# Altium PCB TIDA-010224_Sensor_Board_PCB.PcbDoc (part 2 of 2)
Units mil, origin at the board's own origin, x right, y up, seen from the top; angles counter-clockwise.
Board outline 1083.05 x 1167.48 mil, 4 copper layers (L1-Top Layer, L2-GND Layer, L3-PWR Layer, L4-Bottom Layer), stack 61.6 mil thick; 74 components, 35 nets, 283 pads, 146 vias.
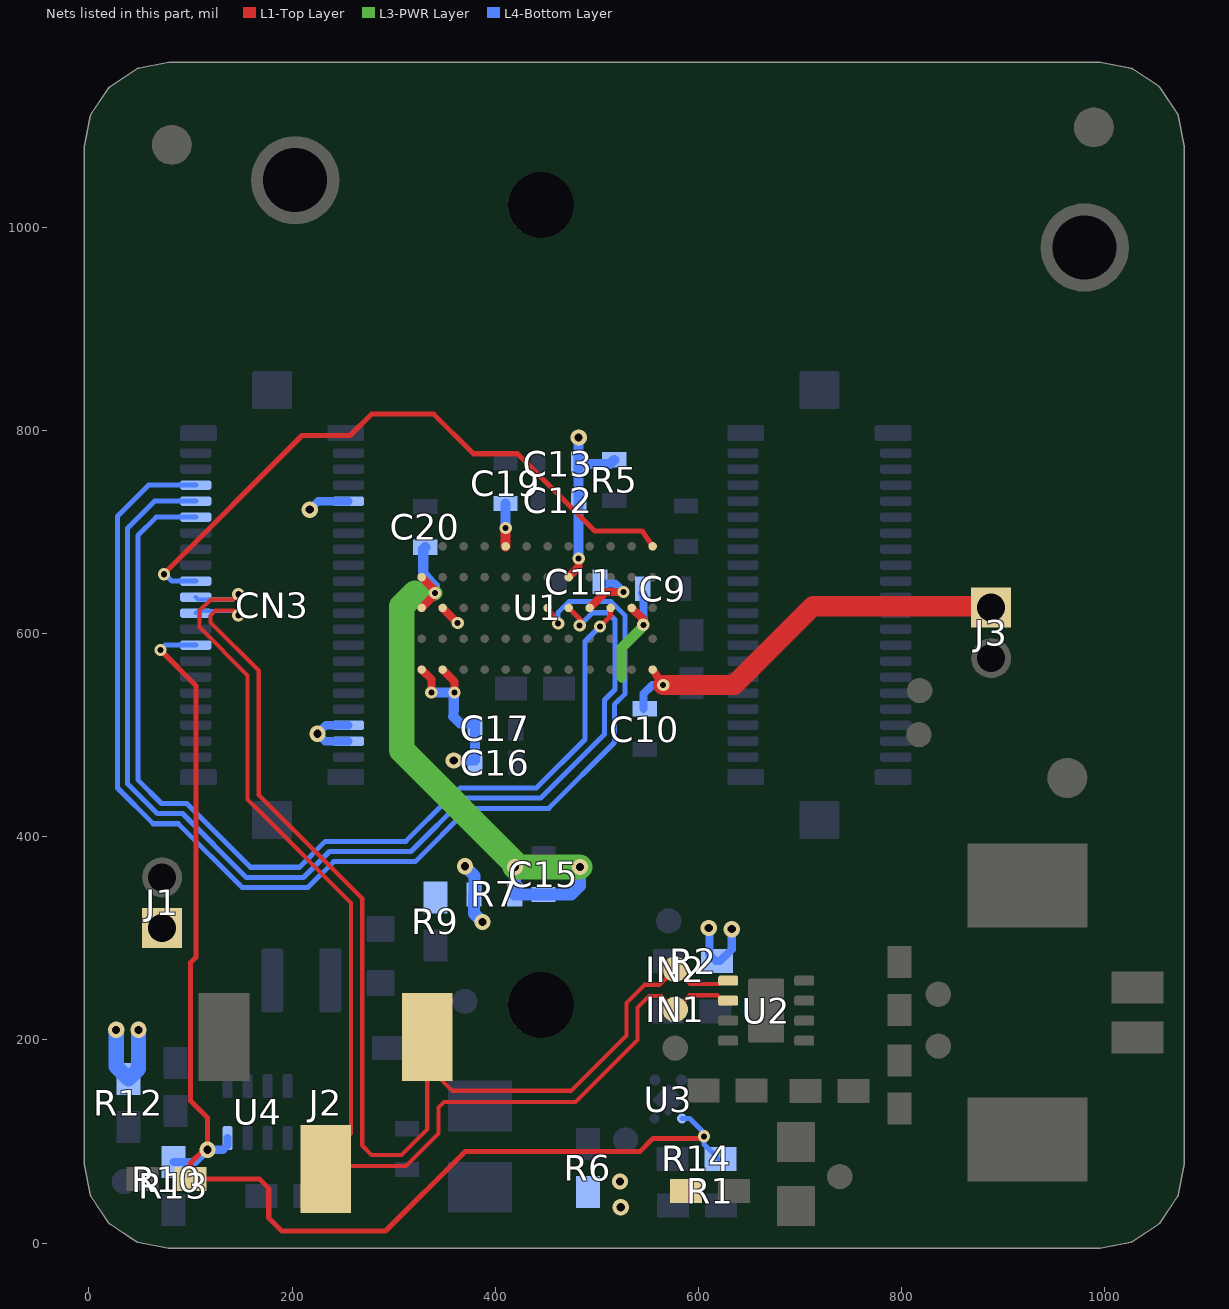
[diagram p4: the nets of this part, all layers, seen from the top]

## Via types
v1: diameter 16, hole 8, L1-Top Layer to L4-Bottom Layer, tented both sides, 103 vias
v2: diameter 12, hole 6, L1-Top Layer to L4-Bottom Layer, tented both sides, 40 vias
v3: diameter 20, hole 8, L1-Top Layer to L4-Bottom Layer, tented top, 2 vias
v4: diameter 20, hole 8, L1-Top Layer to L4-Bottom Layer, 1 vias

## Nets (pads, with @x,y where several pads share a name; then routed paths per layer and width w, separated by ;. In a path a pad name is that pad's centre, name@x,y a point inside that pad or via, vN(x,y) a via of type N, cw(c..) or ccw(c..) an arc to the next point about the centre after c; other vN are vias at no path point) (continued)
SN_IN1: CN3.21 IN1.1 J2.2 U2.6 | length 1239.7
  L1-Top Layer w4: v2(147,638.67) 142,633.67 119.89,633.67 108.74,622.53 108.74,606.29 156.11,558.92 156.11,436.64 167.11,425.64 258,334.76 258,107.8 233,82.8 J2.2@233,73.08 233,63.08 245.92,76 312,76 344,108 344,133.54 349.46,139 479,139 540,200 540,232 551.34,243.34 563.66,243.34 IN1.1@577,230 591,244 618.6,244 623.76,238.84 U2.6@629.21,238.84
  L4-Bottom Layer w4: CN3.21@105.11,635.81 107.49,633.44 141.77,633.44 v2(147,638.67)
SN_IN2: CN3.19 IN2.1 J2.3 U2.5 | length 1200.8
  L1-Top Layer w4: v2(147,618) 142.33,622.67 124.45,622.67 119.74,617.97 119.74,610.85 167.11,563.48 167.11,441.2 269,339.31 269,201.79 269,179.28 269,96 278,87 307.44,87 333,112.56 J2.3@333,175 ; J2.3@333,193 J2.3@333,175 ; U2.5@629.21,258.53 623.53,258.53 620,255 591.61,255 IN2.1@577,269.61 561.74,254.34 546.79,254.34 529,236.56 529,204.56 474.44,150 358,150 J2.3@333,175
  L4-Bottom Layer w4: CN3.19@105.11,620.06 107.49,622.44 142.56,622.44 v2(147,618)
SN_LDO_EN: CN3.15 R10.2 R13.2 R14.2 U3.3 U4.4 | length 1294.7
  L1-Top Layer w5: v2(70.31,583.87) 105.2,548.99 105.2,281.22 100,276.03 100,140.19 116.65,123.54 v1(116.65,92) 112.97,92 100,79.03 R10.2@100,63 ; R10.2@101.94,63 168,63 177,54 177,24.86 189.86,12 291.92,12 370.03,90.11 542.11,90.11 555,103 v2@604,103
  L4-Bottom Layer w5: v2(70.31,583.87) 75.01,588.57 CN3.15@105.11,588.57 ; U3.3@583.8,122.72 591.22,122.72 603.29,110.65 v2@603.29,103.71 ; v2(605.29,105.17) 605.29,97.25 R14.2@619.54,83
  L4-Bottom Layer w8: R13.2@83.28,80 104.65,80 v1(116.65,92) 132.13,92 136.47,96.34 U4.4@136.47,103.41
SN_PWDN: CN3.23 U1.A12 | length 636.5
  L1-Top Layer w5: v2(73.76,658.38) 73.76,659 209.76,795 257,795 278,816 339.46,816 378.46,777 421.8,777 497.78,701.01 544.5,701.01 U1.A12@554.83,685.85
  L4-Bottom Layer w5: v2(73.76,658.38) 74.91,658.38 81.73,651.56 CN3.23@105.11,651.56
SN_RST#: CN3.31 U1.C10 | length 974.2
  L1-Top Layer w5: v2@501.83,605.83 513.5,617.5 U1.C10@513.5,625.22
  L4-Bottom Layer w5: CN3.31@105.11,714.55 66.18,714.55 48.08,696.45 48.08,456.19 71.46,432.81 96.24,432.81 120.45,408.59 159.04,370 207.13,370 232.63,395.5 311.86,395.5 354.36,438 355.36,438 365.36,448 440.36,448 488.12,495.76 488.12,592.12 v2(503,607)
SN_SIO_C: CN3.33 U1.C8 | length 1078.5
  L1-Top Layer w5: U1.C8@472.16,625.22 484.86,612.51 483,610.65 v2(483,608)
  L4-Bottom Layer w5: CN3.33@105.11,730.3 64.55,730.3 38.08,703.83 38.08,452.04 67.32,422.81 92.09,422.81 154.9,360 211.28,360 236.78,385.5 317,385.5 369.5,438 444.5,438 507.35,500.85 507.35,534.54 517.73,544.91 517.73,613.45 510.68,620.5 495.5,620.5 v2(483,608)
SN_SIO_D: CN3.35 U1.C7 | length 1180.5
  L1-Top Layer w5: U1.C7@451.49,625.22 v2(461.82,610.06)
  L4-Bottom Layer w5: CN3.35@105.11,746.05 58.64,746.05 28.08,715.49 28.08,447.9 63.18,412.81 87.95,412.81 150.76,350 215.42,350 240.92,375.5 321.14,375.5 373.64,428 452.61,428 517.35,492.74 517.35,530.39 527.73,540.77 527.73,617.59 513.95,631.37 472.28,631.37 461.82,620.91 v2(461.82,610.06)
V1P8: C11.2 C12.2 C13.2 C19.2 CN3.4 CN3.6 R5.2 U1.A5 U1.B8 U1.C2 U1.C9 | length 371.5
  L1-Top Layer w8: U1.C2@348.14,625.22 v2@361.3,612.06 ; U1.B8@472.16,655.54 482,665.38 481.56,665.82 482,666.26 v2(482,674) ; U1.C9@492.83,625.22 508.6,641 v2(526,641) 524.16,641 v2@523.46,640.3
  L1-Top Layer w10: U1.A5@410.15,685.85 v2(410.15,703.85)
  L4-Bottom Layer w8: CN3.4@255.51,494.08 232.38,494.08 v1(225,501.46) 233.36,509.83 CN3.6@255.51,509.83 ; C11.2@507.5,649.17 517.83,649.17 v2(526,641)
  L4-Bottom Layer w10: C19.2@410,728 410,704 v2(410.15,703.85) ; v2@482,673.88 C12.2@482,731 C13.2@482,767 ; v1(482,793) C13.2@482,767 ; R5.2@517,771 513,767 C13.2@482,767
  other v2: 362.92,610.36
V2P8_AVDD: C9.2 C10.2 C16.2 C17.2 J3.1 R2.1 R7.2 R9.1 U1.C11 U1.E1 U1.E2 U1.E12 | length 833.6
  L1-Top Layer w8: U1.E1@327.47,564.59 337,555.06 v2(337,542) ; U1.E2@348.14,564.59 359.9,552.84 v2(359.9,541.95) ; U1.C11@534.16,625.22 545.65,613.73 v2(545.65,608.64) ; U1.E12@554.83,564.59 v2(565.17,549.43)
  L1-Top Layer w20: v2(565.17,549.43) 635.09,549.43 712.56,626.9 J3.1@875,626.9
  L3-PWR Layer w10: 524,557 524,585.65 544.5,606.14 545.65,607.3 v2(545.65,608.64)
  L4-Bottom Layer w8: C9.2@545,640 544.5,639.5 545.65,638.34 v2(545.65,608.64) ; C10.2@545.98,526 545.98,540.8 554.62,549.43 v2(565.17,549.43) ; v1(610.07,310.3) 610.63,309.75 610.63,284.45 610.35,284.17 616.92,277.6 R2.1@618.25,277.6 621.01,277.6 632.63,289.21 v1(632.63,309.06)
  L4-Bottom Layer w10: v2(337,542) 345.24,542 345.29,541.95 v2(359.9,541.95) 359.9,539.53 359,538.63 359,525.37 ; v1(359,475) 380,475 380,511.54 365.3,511.54 358.48,518.36 358.93,518.81 358.93,524.49 359.02,524.58 359.02,525.35
  L4-Bottom Layer w12: v1(370.04,371.01) 379.39,361.66 379.39,344.38 379,343.99 379.39,343.61 R7.2@379,343.22 379,324.61 v1(387.39,316.22)
V3P3: CN3.34 J1.1 R1.2 R6.2 R12.2 | length 147.5
  L4-Bottom Layer w8: v1(217.36,722) 225.66,730.3 CN3.34@255.51,730.3
  L4-Bottom Layer w15: v1(26.78,210) 26.78,173.84 R12.2@39,161.62 48.86,171.48 v1(48.86,210)
  other v1: 523.46,35.37 522.69,60.71
VPP: C15.2 C20.2 R7.1 U1.B1 U1.C1 | length 610.1
  L1-Top Layer w8: U1.C1@327.47,625.22 340.64,638.39 v2(340.64,639.99) 340.64,642.37 U1.B1@327.47,655.54
  L3-PWR Layer w15: 320.9,639.99 v2(340.64,639.99)
  L3-PWR Layer w25: 320.9,639.99 308,627.09 308,485.13 419.39,373.74 v1(419.39,370.22) v1(483.22,370.22)
  L4-Bottom Layer w10: C20.2@331,685 329,683 329,658.85 331.91,655.94 331.91,655.49 340.64,646.76 v2(340.64,639.99)
  L4-Bottom Layer w12: v1(419.39,370.22) 419.39,343.61 R7.1@419,343.22 C15.2@447.39,343.22 474.63,343.22 483.22,351.8 v1(483.22,370.22)
pads on no net: CN1.3 CN1.4 CN2.1 CN2.2 CN2.3 CN2.4 CN2.5 CN2.6 CN2.7 CN2.8 CN2.9 CN2.10 CN2.11 CN2.12 CN2.13 CN2.14 CN2.15 CN2.16 CN2.17 CN2.18 CN2.19 CN2.20 CN2.21 CN2.22 CN2.23 CN2.24 CN2.25 CN2.26 CN2.27 CN2.28 CN2.29 CN2.30 CN2.31 CN2.32 CN2.33 CN2.34 CN2.35 CN2.36 CN2.37 CN2.38 CN2.39 CN2.40 CN3.3 CN3.5 CN3.7 CN3.9 CN3.11 CN3.13 CN3.25 CN3.27 CN3.29 CN3.30 CN3.32 CN3.36 CN3.37 CN3.38 FID1.1 FID2.1 FID3.1 FID4.1 FID5.1 FID6.1 U1.A3 U1.A6 U1.A9 U1.A10 U1.B6 U1.B7 U1.B9 U1.C5 U1.C6 U1.D3 U1.D4 U1.D5 U1.D6 U1.D7 U1.D8 U1.D9 U2.9@666.62,211.28 U2.9@666.62,246.72

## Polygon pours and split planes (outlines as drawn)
GND on L4-Bottom Layer "L4-BOTTOM_LAYER_GND_P095" (solid, remove dead copper, pour order 95): 16,1091.19 62.27,1137.47 990.77,1137.47 cw(c990.77,1080.38) 1047.78,1077.5 1047.78,79.95 cw(c993.37,79.93) 1031.83,41.44 cw(c993.33,79.93) 993.33,25.49 40.51,25.49 16,50
V2P8_AVDD on L4-Bottom Layer "L4-Bottom Layer-V2P8_AVDD" (solid, remove dead copper, pour order 46): 321.14,375.5 321.14,329.3 329.44,321 385,321 389,325 389,375.99 381.99,383 328.64,383
NetFB1_2 on L4-Bottom Layer "L4-Bottom Layer-NetFB1_2" (solid, remove dead copper, pour order 26): 273.42,297.44 276.09,294.78 305.22,294.78 326,274 352,274 355,277 355,309.78 351.78,313 322.86,313 311.25,324.61 276.02,324.61 273.42,322
Net2P8V_1 on L4-Bottom Layer "L4-BOTTOM_LAYER_NET2P8V_1_P093" (solid, pour order 93): 228.67,274 228.67,287.67 232,291 292.24,291 301.96,281.29 301.96,260.83 307.79,255 317.15,255 339.3,255 342.8,251.51 342.8,222.8 319,199 319,170 335,154 335,105.19 329.81,100 286.41,100 269.12,100 266,103.12 266,136.69 259.68,143 191.55,143 188,146.55 188,169.78 192.82,174.6 218.83,174.6 228.67,184.44
Net3.3V_1 on L4-Bottom Layer "L4-BOTTOM_LAYER_NET3.3V_1_P070" (solid, pour order 70): 563.43,116.36 563.43,123.91 558.02,129.32 513.68,129.32 459.36,129.32 455.8,125.76 455.8,87.75 463.6,79.95 538.65,79.95 547,71.6 547,27.37 553.37,21 585.32,21 591.46,27.14 591.46,87.28 591.49,88.3 591.49,94.35 589.61,96.22 583.56,96.22 579.1,100.68
Net3P3V_1 on L4-Bottom Layer "L4-BOTTOM_LAYER_NET3P3V_1_P066" (solid, pour order 66): 52,95.92 60.22,87.71 60.22,59.51 65.57,54.15 100.99,54.15 108,61.16 108,66.05 117.89,75.93 145.63,75.93 146.72,77.01 167.01,77.01 170.98,80.98 170.87,110 180.31,110 180.31,69.69 186.89,63.11 186.89,15 40,15 15,40 15,132.04 30,132.04 49,132 52,129
V3P3 on L4-Bottom Layer "L4-BOTTOM_LAYER_V3P3_P002" (solid, pour order 2): 472.34,69.34 532.44,69.34 537,64.78 537,25.59 530.3,18.89 468.64,18.89 463.08,24.45 463.08,60.08
NetC18_1 on L4-Bottom Layer "L4-BOTTOM_LAYER_NETC18_1_P038" (solid, pour order 38): 324.62,175.79 324.62,202.3 326,203.68 359.32,203.68 404,159 414,159 425,148 425,106 418,99 353.61,99 349,103.61 349,151.41
Net2.8V_1 on L4-Bottom Layer "L4-BOTTOM_LAYER_NET2.8V_1_P004" (solid, pour order 4): 545.74,148.68 551.28,148.68 566.1,163.49 566.1,171.32 585.85,191.07 585.93,194.37 585.93,289.07 584,291 547,291 541,285 541,153.41
GND on L1-Top Layer "L1-TOP_LAYER_GND_P091" (solid, remove dead copper, pour order 91): 26.55,1101.74 57.45,1132.65 1007.57,1132.65 cw(c1007.58,1123.83) 1011,1131.96 cw(c988.65,1077.23) 1047.78,1077.5 1047.78,77.37 cw(c1002.2,65.07) 1035,31.11 cw(c1011.29,60.73) 993.92,27 54,27 26.55,54.45
V3P3 on L1-Top Layer "L1-TOP_LAYER_V3P3_P088" (solid, pour order 88): 512,69.34 512,30.41 522.41,20 594.7,20 608.22,33.52 608.22,76.11 592.98,91.35 534.01,91.35
NetC1_2 on L1-Top Layer "L1-TOP_LAYER_NETC1_2_P089" (solid, remove dead copper, pour order 89): 641,193.98 641,202.38 636.42,206.97 614.65,206.97 603.86,196.18 603.86,178.57 588.61,163.32 588.61,138.57 614.15,113.03 614.15,21.38 620.47,15 743,15 766,38 766,161.57 722.23,205.34 695.37,205.34 692,201.97 692,191.95 694.74,189.21 713.47,189.21 733,169.69 733,147.85 733,73 641,73
no net on L1-Top Layer "Top Layer-No Net" (solid, pour order 96): 258,313.74
V3P3 on L3-PWR Layer "L3-PWR_LAYER_V3P3_P082" (solid, pour order 82): 19.14,808.64 35.96,825.46 212.52,825.46 232,805.98 232,675.23 205,648.23 205,461.87 263,403.87 263,374 263,121.67 282.33,102.33 290.37,94.3 533.68,94.3 539.42,88.56 539.42,24.87 533.79,18.87 146.12,18.87 19.14,145.87 19.14,534.14
V2P8_AVDD on L3-PWR Layer "L3-PWR_LAYER_V2P8_AVDD_P086" (solid, remove dead copper, pour order 86): 340.54,565 319.5,543.97 319.5,50.51 355.01,15 989,15 1054.38,80.38 1054.38,600.62 999.07,655.93 581.39,655.93 490.46,565
V1P8 on L3-PWR Layer "L3-PWR_LAYER_V1P8_P084" (solid, remove dead copper, pour order 84): 219.95,474 210,483.95 210,643.28 238,671.28 238,1125 252,1139 540.27,1139 993.54,1139 1058,1074.54 1058,713 1020,675 589.27,675 482.27,568 331.52,568 315,551.48 315,488.52 300.48,474
no net on L3-PWR Layer "PWR Layer-No Net" (solid, pour order 87): 81.02,477.13
no net on Bottom Overlay (solid, pour order 48): 329,393
GND on L2-GND Layer "L2-GND_LAYER_GND_P074" (solid, remove dead copper, pour order 74): 26.55,1101.74 56.77,1131.96 993.32,1131.96 cw(c993.33,1077.51) 1031.83,1116.01 cw(c993.33,1077.51) 1047.78,1077.5 1047.78,79.95 cw(c993.33,79.95) 1031.83,41.44 cw(c993.32,79.95) 993.32,25.49 55.51,25.49 26.55,54.45

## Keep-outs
Keep-Out Layer:
  circle w1: c445.14,234.34 r62
  circle w1: c445.14,1021.75 r62
  text ".Layer_Name" at -2909.61,-3439.08 h60

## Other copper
L1-Top Layer:
  region net SN_CLK: 419,753
  text ".Layer_Name" at -2909.61,-3439.08 h60
L2-GND Layer:
  text ".Layer_Name" at -2891,-3432.01 h60
L3-PWR Layer:
  text ".Layer_Name" at -2878,-3434.01 h60
L4-Bottom Layer:
  pour cut-out: 637.88,102.81 637.88,111.86 611.93,137.8 598.52,137.8 598.52,117.12 612.83,102.81
  pour cut-out: 120.7,783 152,783 152,456 120.7,456
  pour cut-out: 239.93,783.31 203,783.31 203,455.25 239.93,455.25
  pour cut-out: 778.5,783.31 741.57,783.31 741.57,455.25 778.5,455.25
  pour cut-out: 659.27,783 690.57,783 690.57,456 659.27,456
  text ".Layer_Name" at -2909.61,-3439.08 h60

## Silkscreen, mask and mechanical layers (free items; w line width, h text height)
Top Overlay:
  lines w6: 508,144.42 508,144.95 529.5,166.44 544.9,166.44 ; 544.9,176 544.9,202.36 ; 566.98,286.07 552.82,286.07 544.9,278.15 544.9,166.44 ; 570.01,173.91 565.45,173.91 557.98,166.44 544.9,166.44 ; 587.97,285.65 593.48,285.65 601.52,277.61 601.52,190.83 601.52,188.99 601.03,188.99 591.57,179.53 ; 110.23,293.4 110.23,962.69 366.13,962.69 366.13,1021.43 cw(c444.87,1021.75) 523.61,1021.43 523.61,962.69 779.52,962.69 779.52,293.4 523.61,293.4 523.61,234.66 cw(c444.87,234.34) 366.13,234.66 366.13,293.4 110.23,293.4 ; 149.6,332.77 740.15,332.77 740.15,923.32 149.6,923.32 149.6,332.77 ; 412.26,29.22 424.48,17 494,17 506,29 506,146.42 504.42,148 412.26,148 412.26,29.22
  lines w10: 749,119 749,111.8 756.8,104 ; 758.31,54.45 769.55,54.45 781,43
  text ".PRJ_Number" at 258,1116.76 h30
  text "2.8V" at 967.08,611.25 h25
  text "GND" at 970,558.11 h25
  text "DVDD" at 835,484.33 h25
  text "3.3V" at 12,244 h25
  text "IN2" at 298,205 h30 r90
  text "EN" at 197,198 h30 r90
  text "GND" at 37,132 h30 r90
  text "IN1" at 186.89,15 h30 r90
  text ".Layer_Name" at -2909.61,-3439.08 h60
Bottom Overlay:
  lines w0: 948.04,83.62 948.04,84
  lines w6: 11,232 7,228 7,68 14,61 ; 379,255.95 388,275 ; 523.88,123.52 523.88,157.57 515.44,166 515.44,175.31 ; 584.01,330.71 586,336 ; 515.44,175.31 516.65,175.31 520.71,171.24 511.38,171.24 515.44,175.31
  text ".Layer_Name" at -2909.61,-3439.08 h60
Top Paste:
  text ".Layer_Name" at -2909.61,-3439.08 h60
Bottom Paste:
  text ".Layer_Name" at -2909.61,-3439.08 h60
Top Solder:
  text ".Layer_Name" at -2909.61,-3439.08 h60
  text ".Layer_Name" at -2909.61,-3439.08 h60
Bottom Solder:
  region: 550.53,114.55 564.14,114.55 564.14,125.17 555.09,134.21 550.53,134.21
  region: 589.7,114.2 576.09,114.2 576.09,124.82 585.14,133.86 589.7,133.86
  region: 589.92,167.68 576.31,167.68 576.31,157.06 585.35,148.02 589.92,148.01
  region: 550.48,167.68 564.08,167.68 564.08,157.06 555.04,148.02 550.48,148.01
  text ".Layer_Name" at -2909.61,-3439.08 h60
Drill Guide:
  text ".Layer_Name" at -2909.61,-3439.08 h60
M1 Board Outline:
  lines w10: 48.86,1151.01 23.31,1133.94 ; 0.25,78.74 6.24,48.6 ; 0.25,78.74 6.24,48.6 ; 0.25,78.74 0.25,1078.26 ; 0.25,1078.26 6.24,1108.39 ; 0.25,1078.26 6.24,1108.39 ; 6.24,48.6 23.31,23.05 ; 6.24,48.6 23.31,23.05 ; 6.24,1108.39 23.31,1133.94 ; 6.24,1108.39 23.31,1133.94 ; 23.31,23.05 48.86,5.98 ; 23.31,23.05 48.86,5.98 ; 23.31,1133.94 49.64,1151.52 79.45,1157.45 994.52,1157.45 ; 48.86,5.98 78.99,-0.01 ; 48.86,5.98 78.99,-0.01 ; 79,0 994.52,0 ; 994.52,0 1024.66,5.99 ; 994.52,0 1024.66,5.99 ; 994.52,1157.45 1024.66,1151.46 ; 994.52,1157.45 1024.66,1151.46 ; 1024.66,5.99 1050.21,23.06 ; 1024.66,5.99 1050.21,23.06 ; 1024.66,1151.46 1050.21,1134.39 ; 1024.66,1151.46 1050.21,1134.39 ; 1050.21,23.06 1067.28,48.61 ; 1050.21,23.06 1067.28,48.61 ; 1050.21,1134.39 1067.28,1108.85 ; 1050.21,1134.39 1067.28,1108.85 ; 1067.28,48.61 1073.27,78.74 ; 1067.28,48.61 1073.27,78.74 ; 1067.28,1108.85 1073.27,1078.72 ; 1067.28,1108.85 1073.27,1078.72 ; 1073.27,78.74 1073.27,1078.72
M2 Board Dimensions:
  rectangle: -3361.61,-2980.59 -2986.61,-2855.59
  rectangle: -3486.61,-2855.59 -3361.61,-2730.59
  lines w7: -3486.61,-2855.59 -2486.61,-2855.59 ; -3361.61,-2980.59 -3361.61,-2730.59 ; -3236.61,-2980.59 -3236.61,-2730.59 ; -2986.61,-2980.59 -2986.61,-2730.59 ; -2736.61,-2980.59 -2736.61,-2730.59 ; -3486.61,-2980.59 -3486.61,-2730.59 -2486.61,-2730.59 -2486.61,-2980.59 -3486.61,-2980.59
M3 3D STEP Top:
  text ".Layer_Name" at -2909.61,-3439.08 h60
M4 3D STEP Bottom:
  text ".Layer_Name" at -2909.61,-3439.08 h60
M5 Assembly Top:
  circle w10: c879,618.44 r9.85
  lines w10: -3778.61,-3510.76 2821.39,-3510.76 ; -3778.61,-3307.42 2823.39,-3307.42 ; -3778.61,-3104.09 -3778.61,-3714.09 226.39,-3714.09 2823.39,-3714.09 2823.39,-3104.09 -3778.11,-3104.09 -3778.11,-3714.09 -2202.61,-3714.09 ; -1313.61,-3714.09 -1313.61,-3104.09 ; -46.61,-3307.42 -46.61,-3104.09 ; 793.39,-3307.42 793.39,-3104.09 ; 1415.39,-3720.59 1415.39,-3517.76
  text "COMPONENTS MARKED 'DNP' SHOULD NOT BE POPULATED." at -2333.11,-2899.09 h18
  text "ASSEMBLY VARIANT:" at -2333.61,-3014.59 h18
  text ".VariantName" at -1297.61,-3014.59 h18
  text ".PRJ_Number" at -1032,-3235 h18
  text "PCB VIEWED FROM TOP SIDE" at -3715.11,-3236.26 h18
  text "BOARD #:" at -1238.61,-3236.26 h18
  text "REV:" at 151.39,-3236.26 h18
  text ".PCB_Rev" at 246,-3237 h18
  text "SVN REV:" at 989.39,-3236.26 h18
  text ".VersionControl_RevNumber" at 1495.39,-3236.26 h18
  text ".Layer_Name" at -2908,-3434.01 h18
  text "LAYER NAME =" at -3715.11,-3439.08 h18
  text "TID #:" at -1238.61,-3439.59 h18
  text ".TID" at -1105,-3440 h18
  text "PLOT NAME =" at -3715.11,-3644.92 h18
  text ".plot_File_Name" at -2909.61,-3644.92 h18
  text "GENERATED    :" at -1236.61,-3644.92 h18
  text ".Print_Date" at -367.11,-3644.92 h18
  text ".Print_Time" at 361.89,-3644.92 h18
  text "TEXAS INSTRUMENTS" at 1626.39,-3644.92 h18
M6 Assembly Bottom:
  circle w10: c132.13,177.92 r5.39
  lines w10: -3779.11,-3307.92 2822.89,-3307.92 ; -3777.11,-3511.26 2822.89,-3511.26 ; -2371.11,-3721.09 -2371.11,-3518.26 ; -1749.11,-3307.92 -1749.11,-3104.59 ; -909.11,-3307.92 -909.11,-3104.59 ; 357.89,-3714.59 357.89,-3104.59 ; 1246.89,-3714.59 2822.39,-3714.59 2822.39,-3104.59 -3779.11,-3104.59 -3779.11,-3714.59 -1182.11,-3714.59 2822.89,-3714.59 2822.89,-3104.59
  text "COMPONENTS MARKED 'DNP' SHOULD NOT BE POPULATED." at 2615.39,-2898.59 h18
  text ".VariantName" at 1571.39,-3014.59 h18
  text "ASSEMBLY VARIANT:" at 2610.39,-3014.59 h18
  text ".PRJ_Number" at 99.39,-3233.76 h18
  text ".VersionControl_RevNumber" at -2451.11,-3236.76 h18
  text "SVN REV:" at -1945.11,-3236.76 h18
  text ".PCB_Rev" at -1209.61,-3236.76 h18
  text "REV:" at -1107.11,-3236.76 h18
  text "BOARD #:" at 282.89,-3236.76 h18
  text "PCB VIEWED FROM BOTTOM SIDE" at 2759.39,-3236.76 h18
  text ".Layer_Name" at 2509,-3413 h18
  text "LAYER NAME =" at 2754,-3414 h18
  text ".TID" at 142.39,-3435.09 h18
  text "TID #:" at 282.89,-3440.09 h18
  text "TEXAS INSTRUMENTS" at -2582.11,-3645.42 h18
  text ".Print_Time" at -1317.61,-3645.42 h18
  text ".Print_Date" at -588.61,-3645.42 h18
  text "GENERATED    :" at 280.89,-3645.42 h18
  text ".plot_File_Name" at 1953.89,-3645.42 h18
  text "PLOT NAME =" at 2759.39,-3645.42 h18
M9 Title Sheet:
  drawing of 57 lines, arcs and shapes, not listed
  text "1" at -2746.78,5455.91 h70
  text "2" at -251.11,5455.91 h70
  text "3" at 2238.23,5455.91 h70
  text "4" at 4744.9,5455.91 h70
  text "5" at 7243.89,5455.91 h70
  text "6" at 9748.89,5455.91 h70
  text "A" at -3903.11,4312.91 h70
  text "A" at 10896.89,4312.91 h70
  text "A" at 10898.91,4312.13 h70
  text "B" at -3903.11,1932.91 h70
  text "B" at 10896.89,1932.91 h70
  text "B" at 10898.91,1932.13 h70
  text "C" at -3903.11,-442.09 h70
  text "C" at 10896.89,-442.09 h70
  text "C" at 10898.91,-442.87 h70
  text "PROJECT TITLE:" at 7856.89,-2303.09 h45
  text ".PRJ_Title" at 7906.89,-2436.42 h70
  text "DESIGNED FOR:" at 7856.89,-2604.09 h45
  text ".PRJ_Customer" at 7906.89,-2744.09 h70
  text "D" at -3903.11,-2812.09 h70
  text "D" at 10896.89,-2812.09 h70
  text "FILE NAME:" at 7856.89,-2904.09 h45
  text ".PCB_File_Name_No_Path" at 7906.89,-3024.09 h70
  text "Texas Instruments (TI) and/or its licensors do not warrant the accuracy or completeness of this specification" at 2887.39,-3185.93 h45
  text "ENGINEER:" at 7856.89,-3194.09 h45
  text "LAYOUT BY:" at 9361.89,-3194.09 h45
  text "or any information contained therein. TI and/or its licensors do not warrant that this design will meet" at 2842.4,-3298.59 h45
  text ".PRJ_Engineer" at 7906.89,-3349.08 h70
  text ".PCB_Layout" at 9412.39,-3349.08 h70
  text "the specifications, will be suitable for your application or fit for any particular purpose, or will operate in" at 2842.4,-3411.26 h45
  text "ALTIUM DESIGNER VERSION:" at 9361.89,-3504.09 h45
  text "an implementation. TI and/or its licensors do not warrant that the design is production worthy. You should" at 2842.4,-3523.92 h45
  text "completely validate and test your design implementation to confirm the system functionality for your application." at 2887.39,-3636.59 h45
  text ".print_Scale" at 7906.89,-3637.42 h70
  text ".Application_BuildNumber" at 9412.39,-3637.42 h70
  text "1" at -2746.78,-3844.09 h70
  text "2" at -251.11,-3844.09 h70
  text "3" at 2238.23,-3844.09 h70
  text "4" at 4744.9,-3844.09 h70
  text "5" at 7243.89,-3844.09 h70
  text "6" at 9748.89,-3844.09 h70
M10 Fab Notes:
  drawing of 243 lines, arcs and shapes, not listed
  text "DESIGN INFORMATION" at 8884.86,4219.35 h60
  text "(REFER ALSO ARRAY/PANEL PROFILING INFORMATION)" at 8533.35,4053.28 h60
  text "BOARD SIZE" at 7847.35,4048.99 h60
  text "1073.02mil" at 8323.37,3934.63 h60
  text "X" at 8815.35,3921.17 h60
  text "1157.45mil" at 9022,3919.99 h60
  text "Number of Layers :" at 8250.34,3723.99 h60
  text "4" at 9322.89,3718.99 h60
  text "4" at 9323.82,3587.2 h60
  text "MIN. TRACK WIDTH:" at 8250.34,3584.99 h60
  text "MIL" at 9501.34,3584.99 h60
  text "4" at 9323.37,3460.63 h60
  text "MIN. CLEARANCE:" at 8250.34,3452.99 h60
  text "MIL" at 9501.34,3452.99 h60
  text "6" at 9325.82,3333.2 h60
  text "MIN. VIA DRILL SIZE:" at 8250.34,3320.99 h60
  text "MIL" at 9501.34,3320.99 h60
  text "EXTERNAL" at 9242.89,3190.99 h60
  text "3 MIL" at 8945.35,3179.28 h60
  text "MINIMUM ANNULAR RING" at 7921.11,3175 h60
  text "PER" at 8121.11,3057 h60
  text "IPC-D-275 CLASS 2 LEVEL C" at 8341.11,3056.99 h60
  text "+/-" at 9436.89,2944 h60
  text "MIL, HOLES" at 9829.34,2944.71 h60
  text "+/-" at 10290.89,2944 h60
  text "REGISTRATION TOLERANCES:" at 7921.11,2938.99 h60
  text "METAL" at 9120.89,2938.99 h60
  text "5" at 9697.09,2939 h60
  text "3" at 10530.09,2939 h60
  text "MIL" at 10646.34,2938.99 h60
  text "MATERIAL:" at 7846.35,2729.54 h60
  text "FR-4 High Tg" at 8832.79,2589.2 h60
  text "X" at 8673.89,2580.99 h60
  text "FR-408" at 8267.35,2580.63 h60
  text "OTHER" at 9755.35,2580.63 h60
  text "63 MIL (1.6mm) +/-10%" at 8587.45,2417.92 h60
  text "THICKNESS:" at 7921.11,2413.63 h60
  text "X" at 8459.28,2413.63 h60
  text "OTHER" at 9872.35,2413.63 h60
  text "TOLERANCE:" at 7921.11,2255.63 h60
  text "X" at 8760.42,2255.63 h60
  text "ANSI IPC-6012 TYPE 3 CLASS 2" at 8947.36,2255.63 h60
  text "OTHER +/-" at 8947.35,2099.63 h60
  text "BOW & TWIST:" at 7921.11,1942.63 h60
  text "X" at 8760.42,1942.63 h60
  text "ANSI IPC-6012 TYPE 3 CLASS 2" at 8947.36,1942.63 h60
  text "OTHER +/-" at 8947.35,1784.13 h60
  text "COPPER THICKNESS (FINISHED):" at 7846.35,1648.63 h60
  text "1.4MIL (1oz)" at 8726.34,1495.92 h60
  text "2MIL (1.4oz)" at 9493.35,1495.92 h60
  text "2.8MIL (2oz)" at 10220.35,1495.92 h60
  text "OUTER:" at 8203.35,1491.63 h60
  text "X" at 8597.89,1490.99 h60
  text "X" at 8593.89,1340.99 h60
  text "1.4MIL (1oz)" at 8726.34,1338.92 h60
  text "2.8MIL (2oz)" at 9493.35,1338.92 h60
  text "N/A" at 10219.89,1339.28 h60
  text "INNER SIGNAL:" at 7914.26,1334.63 h60
  text "DRILLING:" at 7846.35,1195.63 h60
  text "REFERENCE:" at 7921.11,1078.63 h60
  text "X" at 8569.35,1078.63 h60
  text "AS SHOWN" at 8756.34,1078.63 h60
  text "X" at 9470.35,1078.63 h60
  text "NC_DRILL FILES" at 9607.34,1078.63 h60
  text "PTH MIN COPPER THICKNESS:" at 7921.11,920.63 h60
  text "X" at 9271.35,920.63 h60
  text "1MIL" at 9408.34,920.63 h60
  text "OTHER" at 9905.35,920.63 h60
  text "BOARD FINISH:" at 7846.35,761.63 h60
  text "SILKSCREEN:" at 8001.57,643.63 h60
  text "X" at 8950.35,643.63 h60
  text "TOP" at 9076.34,643.63 h60
  text "X" at 9460.35,643.63 h60
  text "BOTTOM" at 9587.34,643.63 h60
  text "SILKSCREEN COLOR:" at 8001.57,476.63 h60
  text "X" at 8949.3,476.63 h60
  text "WHITE" at 9076.34,476.63 h60
  text "OTHER" at 9587.34,476.63 h60
  text "BLUE" at 9793,319.8 h60
  text "X" at 9078.31,308.44 h60
  text "GREEN" at 9205.34,308.44 h60
  text "SOLDER RESIST COLOR:" at 8001.57,306.63 h60
  text "OTHER" at 9825.35,147.44 h60
  text "IMPEDANCE DETAILS - ALL DIMENSIONS IN MILS" at 3100.5,137.5 h60
  text "X" at 9076.06,132.53 h60
  text "MATTE" at 9194.06,132.53 h60
  text "100ohm DIFFERENTIAL" at 3691.5,45.5 h40
  text "IMPEDANCE CONTROL" at 3694.5,8.5 h40
  text "+/- 10%" at 3804.5,-26.5 h40
  text "IMMERSION GOLD (ENIG)" at 8907.34,-41.08 h60
  text "ENEPIG" at 10244.89,-44.37 h60
  text "SURFACE FINISH:" at 7846.35,-45.37 h60
  text "X" at 8720.4,-45.37 h60
  text "TRACE WIDTH / SPACE" at 3667.5,-85.5 h40
  text "LAYER#" at 2970.5,-89.5 h40
  text "LAYER 1 - PRIMARY SIDE - SIGNAL" at 2939.5,-159.5 h40
  text "4.00/7.00" at 3754,-160 h40
  text "IMM. TIN/SILVER OR EQUIV" at 8175.89,-202.37 h60
  text "OTHER" at 9607.35,-202.37 h60
  text "LAYER 2 - GND" at 2944,-254 h40
  text "LAYER 3 - GND" at 2948,-336 h40
  text "ARRAY/PANEL:" at 7846.35,-381.37 h60
  text "X" at 8717,-383 h60
  text "CUT AND TRIM PER MECH LAYER 1" at 8907.35,-385.65 h60
  text "4.00/7.00" at 3756,-420 h40
  text "LAYER 4 - SECONDARY SIDE - SIGNAL" at 2942,-423 h40
  text "N.C. ROUTE" at 8907.34,-537.37 h60
  text "V. SCORE" at 9773.35,-537.37 h60
  text "CERTIFICATION:" at 7846.35,-674.37 h60
  text "MATERIALS AND WORKMANSHIP FOR ALL PCBS" at 8571.35,-674.37 h60
  text "TO MEET OR EXCEED THE REQUIREMENTS OF:" at 8571.35,-772.37 h60
  text "FAB Note:" at 2743.76,-796.49 h150
  text "X" at 8197.85,-908.87 h60
  text "ANSI IPC-A-600F CLASS ->" at 8336.85,-908.87 h60
  text "X" at 9975.9,-908.87 h60
  text "2" at 10094.85,-908.87 h60
  text "1" at 9779.85,-910.37 h60
  text "3" at 10448.85,-910.37 h60
  text "1.ITS AN IMPEDANCE CONTROLLED BOARD" at 2741.15,-924 h60
  text "2.ALL VIAS ARE  TENTED EXCEPT THERMAL VIAS" at 2741.15,-1051.25 h60
  text "X" at 8199.9,-1068.37 h60
  text "UL 94V-0" at 8336.85,-1068.37 h60
  text "X" at 9011.9,-1068.37 h60
  text "RoHS" at 9148.85,-1068.37 h60
  text "OTHER" at 9793.25,-1068.37 h60
  text "PER ORDER" at 10190.31,-1068.37 h60
  text "3.Vendor may adjust soldermask wherever the soldermask pads are same size(1:1)" at 2733.15,-1187.72 h150
  text "VIA TENTING:" at 9063.89,-1202.01 h60
  text "X" at 9826.37,-1205.37 h60
  text "ADDITIONAL REQUIREMENTS:" at 7846.35,-1209.37 h60
  text "YES" at 9613.55,-1211.09 h60
  text "NO" at 9978.36,-1216.31 h60
  text "MICROSECTION:" at 7921.11,-1324.37 h60
  text "YES" at 8826.85,-1324.37 h60
  text "IMPEDANCE CONTROL:" at 9085.89,-1331.01 h60
  text "YES" at 10069.89,-1332.01 h60
  text "X" at 10288,-1332 h60
  text "NO" at 10445.36,-1349.31 h60
  text "As per the manufacturing capabilities and all other soldermask pads  / shall not be modified," at 2919.74,-1425.25 h150
  text "REQUIRED" at 9688.34,-1480.51 h60
  text "BARE BOARD ELEC. TEST:" at 7921.11,-1483.37 h60
  text "NONE" at 9226.85,-1483.37 h60
  text "X" at 9561.35,-1483.37 h60
  text "PER ORDER" at 10280.35,-1483.37 h60
  text "MANUFACTURER'S UL:" at 7921.11,-1640.37 h60
  text "RAIL" at 9086.85,-1644.65 h60
  text "METAL" at 9578.66,-1644.65 h60
  text "X" at 9953.89,-1645.01 h60
  text "SILK" at 10090.34,-1644.65 h60
  text "Provided no adjscent copper is exposed and  no conflict is  produced  / with any stated\"Via tenting/covering requirements\"" at 2919.34,-1659.79 h150
M11 Gerber Information:
  lines w10: -3778.61,-3510.76 2821.39,-3510.76 ; -3778.61,-3307.42 2823.39,-3307.42 ; -3778.61,-3104.09 -3778.61,-3714.09 226.39,-3714.09 2823.39,-3714.09 2823.39,-3104.09 -3778.11,-3104.09 -3778.11,-3714.09 -2202.61,-3714.09 ; -1313.61,-3714.09 -1313.61,-3104.09 ; -46.61,-3307.42 -46.61,-3104.09 ; 793.39,-3307.42 793.39,-3104.09 ; 1415.39,-3720.59 1415.39,-3517.76
  text ".PRJ_Number" at -754,-3223 h50
  text "REV:" at 276.39,-3231.26 h60
  text ".PCB_Rev" at 567.89,-3231.26 h60
  text "ALL ARTWORK VIEWED FROM TOP SIDE" at -3715.11,-3236.26 h60
  text "BOARD #:" at -1238.61,-3236.26 h60
  text "SVN REV:" at 989.39,-3236.26 h60
  text ".VersionControl_RevNumber" at 1495.39,-3236.26 h60
  text "LAYER NAME =" at -3715.11,-3439.08 h60
  text "TID #:" at -1238.61,-3439.59 h60
  text ".TID" at -693.11,-3439.59 h60
  text "PLOT NAME =" at -3715.11,-3644.92 h60
  text ".plot_File_Name" at -2909.61,-3644.92 h30
  text "GENERATED    :" at -1236.61,-3644.92 h60
  text ".Print_Date" at -367.11,-3644.92 h60
  text ".Print_Time" at 361.89,-3644.92 h60
  text "TEXAS INSTRUMENTS" at 1626.39,-3644.92 h60
M12 Stackup:
  drawing of 295 lines, arcs and shapes, not listed
  text "Layer" at 2052.09,3568 h60
  text "Name" at 2462,3568 h60
  text "Material" at 3451.73,3568 h60
  text "Thickness" at 4311.49,3568 h60
  text "Constant" at 4961.33,3568 h60
  text "Board Layer Stack" at 5531.19,3568 h60
  text "1" at 2052.09,3448 h60
  text "Top Overlay" at 2462,3448 h60
  text "2" at 2052.09,3328 h60
  text "Top Solder" at 2462,3328 h60
  text "Solder Resist" at 3451.73,3328 h60
  text "0.30mil" at 4311.49,3328 h60
  text "3.5" at 4961.33,3328 h60
  text "3" at 2052.09,3208 h60
  text "L1-Top Layer" at 2462,3208 h60
  text "Copper" at 3451.73,3208 h60
  text "1.40mil" at 4311.49,3208 h60
  text "4" at 2052.09,3088 h60
  text "Dielectric1" at 2462,3088 h60
  text "FR-4 High Tg" at 3451.73,3088 h60
  text "8.00mil" at 4311.49,3088 h60
  text "4.5" at 4961.33,3088 h60
  text "5" at 2052.09,2968 h60
  text "L2-GND Layer" at 2462,2968 h60
  text "Copper" at 3451.73,2968 h60
  text "1.40mil" at 4311.49,2968 h60
  text "6" at 2052.09,2848 h60
  text "Dielectric 2" at 2462,2848 h60
  text "FR-4 High Tg" at 3451.73,2848 h60
  text "40.00mil" at 4311.49,2848 h60
  text "4.5" at 4961.33,2848 h60
  text "7" at 2052.09,2728 h60
  text "L3-PWR Layer" at 2462,2728 h60
  text "Copper" at 3451.73,2728 h60
  text "1.40mil" at 4311.49,2728 h60
  text "8" at 2052.09,2608 h60
  text "Dielectric 3" at 2462,2608 h60
  text "FR-4 High Tg" at 3451.73,2608 h60
  text "8.00mil" at 4311.49,2608 h60
  text "4.5" at 4961.33,2608 h60
  text "9" at 2052.09,2488 h60
  text "L4-Bottom Layer" at 2462,2488 h60
  text "Copper" at 3451.73,2488 h60
  text "1.40mil" at 4311.49,2488 h60
  text "10" at 2052.09,2368 h60
  text "Bottom Solder" at 2462,2368 h60
  text "Solder Resist" at 3451.73,2368 h60
  text "0.30mil" at 4311.49,2368 h60
  text "3.5" at 4961.33,2368 h60
  text "11" at 2052.09,2248 h60
  text "Bottom Overlay" at 2462,2248 h60
M13 Component Bodies Top:
  text ".Layer_Name" at -2909.61,-3439.08 h60
M14 Component Bodies Bottom:
  text ".Layer_Name" at -2909.61,-3439.08 h60
M15 Courtyards Top:
  text ".Layer_Name" at -2909.61,-3439.08 h60
M16 Courtyards Bottom:
  text ".Layer_Name" at -2909.61,-3439.08 h60
Drill Drawing:
  circle w10: c2081.72,1620.96 r27.63
  lines w10: 2054.09,1234.19 2067.9,1234.19 2067.9,1220.37 2095.53,1220.37 2095.53,1234.19 2109.34,1234.19 2109.34,1261.81 2095.53,1261.81 2095.53,1275.63 2067.9,1275.63 2067.9,1261.81 2054.09,1261.81 2054.09,1234.19 ; 2054.09,1344.69 2109.34,1344.69 2109.34,1399.95 2054.09,1399.95 2054.09,1344.69 ; 2054.09,1469.01 2081.72,1482.83 2109.34,1469.01 2095.53,1496.64 2109.34,1524.27 2081.72,1510.45 2054.09,1524.27 2067.9,1496.64 2054.09,1469.01 ; 2054.09,1772.91 2109.34,1772.91 2081.72,1717.65 2054.09,1772.91
  lines w12: 2004,1183.08 5393.66,1183.08 ; 2004,1804.68 5393.66,1804.68 ; 2341.86,1058.76 2341.86,1929 ; 2673.86,1058.76 2673.86,1929 ; 3310.43,1058.76 3310.43,1929 ; 3569.57,1058.76 3569.57,1929 ; 3944.72,1058.76 3944.72,1929 ; 4827.23,1058.76 4827.23,1929 ; 2004,1058.76 5393.66,1058.76 5393.66,1929 2004,1929 2004,1058.76
  text "Symbol" at 2078.59,1841.97 h72
  text "Quantity" at 2379.16,1841.97 h72
  text "Finished Hole Size" at 2711.16,1841.97 h72
  text "Plated" at 3347.72,1841.97 h72
  text "Hole Type" at 3606.86,1841.97 h72
  text "Drill Layer Pair" at 3982.02,1841.97 h72
  text "Hole Tolerance" at 4864.53,1841.97 h72
  text "2" at 2379.16,1717.65 h60
  text "65.00mil (1.651mm)" at 2711.16,1717.65 h60
  text "NPTH" at 3347.72,1717.65 h60
  text "Round" at 3606.86,1717.65 h60
  text "L1-Top Layer - L4-Bottom Layer" at 3982.02,1717.65 h60
  text "40" at 2379.16,1593.33 h60
  text "6.00mil (0.152mm)" at 2711.16,1593.33 h60
  text "PTH" at 3347.72,1593.33 h60
  text "Round" at 3606.86,1593.33 h60
  text "L1-Top Layer - L4-Bottom Layer" at 3982.02,1593.33 h60
  text "106" at 2379.16,1469.01 h60
  text "8.00mil (0.203mm)" at 2711.16,1469.01 h60
  text "PTH" at 3347.72,1469.01 h60
  text "Round" at 3606.86,1469.01 h60
  text "L1-Top Layer - L4-Bottom Layer" at 3982.02,1469.01 h60
  text "4" at 2379.16,1344.69 h60
  text "27.56mil (0.700mm)" at 2711.16,1344.69 h60
  text "PTH" at 3347.72,1344.69 h60
  text "Round" at 3606.86,1344.69 h60
  text "L1-Top Layer - L4-Bottom Layer" at 3982.02,1344.69 h60
  text "2" at 2379.16,1220.37 h60
  text "63.00mil (1.600mm)" at 2711.16,1220.37 h60
  text "PTH" at 3347.72,1220.37 h60
  text "Round" at 3606.86,1220.37 h60
  text "L1-Top Layer - L4-Bottom Layer" at 3982.02,1220.37 h60
  text "154 Total" at 2379.16,1096.05 h60
  text "FOR 6MIL DRILL +0/-6MIL" at 2012,726.67 h60
  text "FOR 8MIL DRILL +0/-8MIL" at 2014.18,628.57 h60
  text "FOR PTH DRILL +/-3MIL" at 2014.18,524.38 h60
  text "FOR NPTH DRILL +/-2MIL" at 2011,419 h60
  text ".Layer_Name" at -2909.61,-3439.08 h60
M17 Embedded Cavity:
  text ".Layer_Name" at -2909.61,-3439.08 h60
M18 Embedded Assembly:
  text ".Layer_Name" at -2909.61,-3439.08 h60
M19 Embedded Keepout:
  text ".Layer_Name" at -2909.61,-3439.08 h60

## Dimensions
-3486.61,-2980.59 to -2486.61,-2980.59 on M2 Board Dimensions
0.25,1078.26 to 1073.27,1078.72 on M2 Board Dimensions
994.52,1157.45 to 994.52,0 on M2 Board Dimensions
